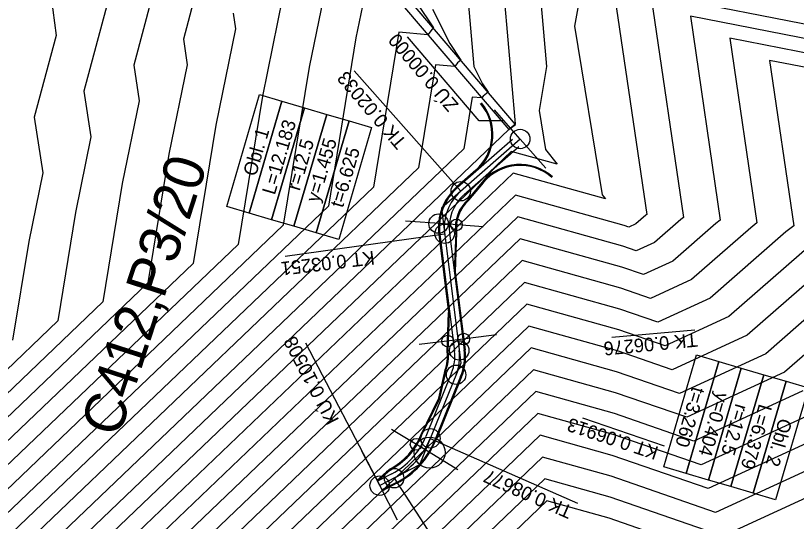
# Model space of a CAD drawing. Extents: x -549394 to -546608, y -1037055 to -1033629.
# Drawn here: x -547510.8 to -547310, y -1036162.3 to -1036032.2 of the extents above; entities that cross this region are included whole.
import ezdxf

# ---------------------------------------------------------------- set-up
doc = ezdxf.new("R2010")
doc.units = 0
for name, color, linetype in [('hlavni_vrst', 7, 'Continuous'), ('hrana_L', 7, 'Continuous'), ('norm_vrst', 7, 'Continuous'), ('POLYGONY_SITUACE_PO', 7, 'Continuous'), ('u_sirka_1_5m', 7, 'Continuous'), ('x_navrh_C412', 7, 'Continuous'), ('x_osa_C412', 7, 'Continuous'), ('x_popis_oblouky_C412', 7, 'Continuous'), ('x_popis_pricne_rezy_C412', 7, 'Continuous'), ('x_popis_velky_C412', 7, 'Continuous')]:
    doc.layers.add(name, color=color, linetype=linetype)

msp = doc.modelspace()

# ---------------------------------------------------------------- linework, layer by layer
at = {"layer": 'hlavni_vrst'}
for p, q in [((-547430.88, -1036023.9), (-547435.28, -1036045.47)), ((-547385.56, -1036022.8), (-547382.3, -1036060.1)), ((-547487.05, -1036028.71), (-547493.18, -1036051.67)), ((-547337.27, -1036032.37), (-547329.59, -1036084.85)), ((-547242.13, -1036051.11), (-547337.27, -1036032.37)), ((-547435.28, -1036045.47), (-547441.94, -1036086.16)), ((-547493.18, -1036051.67), (-547491.39, -1036063.41)), ((-547382.26, -1036060.17), (-547383.95, -1036061.55)), ((-547382.3, -1036060.1), (-547382.27, -1036060.15)), ((-547382.27, -1036060.15), (-547382.26, -1036060.17)), ((-547383.95, -1036061.55), (-547529.34, -1036200.56)), ((-547383.95, -1036061.55), (-547383.95, -1036061.55)), ((-547383.95, -1036061.55), (-547383.95, -1036061.55)), ((-547383.95, -1036061.55), (-547383.95, -1036061.55)), ((-547383.95, -1036061.55), (-547383.95, -1036061.55)), ((-547383.95, -1036061.55), (-547383.95, -1036061.55)), ((-547383.95, -1036061.55), (-547383.95, -1036061.55)), ((-547383.95, -1036061.55), (-547383.95, -1036061.55)), ((-547491.39, -1036063.41), (-547495.36, -1036082.87)), ((-547495.36, -1036082.87), (-547499.92, -1036110.77)), ((-547441.94, -1036086.16), (-547552.56, -1036191.93)), ((-547330.76, -1036085.74), (-547341.74, -1036095.35)), ((-547329.59, -1036084.85), (-547330.76, -1036085.74)), ((-547381.07, -1036089.63), (-547506.12, -1036209.19)), ((-547354.88, -1036096.94), (-547381.07, -1036089.63)), ((-547285.75, -1036091.08), (-547317.86, -1036119.19)), ((-547341.74, -1036095.35), (-547349.34, -1036098.86)), ((-547349.34, -1036098.86), (-547354.88, -1036096.94)), ((-547499.92, -1036110.77), (-547575.78, -1036183.3)), ((-547378.19, -1036117.71), (-547482.89, -1036217.82)), ((-547356.25, -1036123.83), (-547378.19, -1036117.71)), ((-547317.86, -1036119.19), (-547340.07, -1036129.43)), ((-547340.07, -1036129.43), (-547356.25, -1036123.83)), ((-547293.98, -1036143.02), (-547330.8, -1036160)), ((-547375.3, -1036145.78), (-547459.67, -1036226.45)), ((-547357.63, -1036150.72), (-547375.3, -1036145.78)), ((-547330.8, -1036160), (-547357.63, -1036150.72))]:
    msp.add_line(p, q, dxfattribs=at)
at = {"layer": 'hrana_L'}
for p, q in [((-547382.19, -1036060.25), (-547409.46, -1036028.18)), ((-547411.32, -1036029.57), (-547383.95, -1036061.55)), ((-547383.95, -1036061.55), (-547382.19, -1036060.25))]:
    msp.add_line(p, q, dxfattribs=at)
at = {"layer": 'norm_vrst'}
for p, q in [((-547460.45, -1036011.4), (-547467.63, -1036038.31)), ((-547473.75, -1036020.05), (-547480.4, -1036044.99)), ((-547502.52, -1036020.73), (-547500.35, -1036037.36)), ((-547376.33, -1036021.55), (-547374.26, -1036045.33)), ((-547357.62, -1036020.99), (-547348.49, -1036083.4)), ((-547394.78, -1036024.05), (-547392.92, -1036045.34)), ((-547441.87, -1036026.36), (-547447.29, -1036052.95)), ((-547347.44, -1036026.68), (-547339.04, -1036084.12)), ((-547243.31, -1036047.19), (-547347.44, -1036026.68)), ((-547421.58, -1036029.73), (-547423.26, -1036037.99)), ((-547407.54, -1036029.1), (-547403.29, -1036035.43)), ((-547403.54, -1036030.58), (-547399.12, -1036039.45)), ((-547366.24, -1036030.25), (-547367.03, -1036035)), ((-547454.86, -1036031.63), (-547454.25, -1036035.63)), ((-547454.25, -1036035.63), (-547459.31, -1036060.43)), ((-547412.23, -1036036.52), (-547418.74, -1036076.32)), ((-547404.79, -1036037.2), (-547412.23, -1036036.52)), ((-547403.67, -1036035.75), (-547404.79, -1036037.2)), ((-547403.29, -1036035.43), (-547403.67, -1036035.75)), ((-547367.03, -1036035), (-547359.98, -1036078.3)), ((-547500.35, -1036037.36), (-547505.95, -1036058.35)), ((-547467.63, -1036038.31), (-547466.63, -1036044.89)), ((-547423.26, -1036037.99), (-547430.34, -1036081.24)), ((-547327.09, -1036038.06), (-547320.14, -1036085.57)), ((-547240.95, -1036055.02), (-547327.09, -1036038.06)), ((-547399.12, -1036039.45), (-547396.28, -1036043.68)), ((-547397.1, -1036044.35), (-547397.84, -1036045.32)), ((-547396.28, -1036043.68), (-547397.1, -1036044.35)), ((-547316.91, -1036043.75), (-547310.69, -1036086.3)), ((-547239.78, -1036058.94), (-547316.91, -1036043.75)), ((-547480.4, -1036044.99), (-547479.01, -1036054.15)), ((-547466.63, -1036044.89), (-547471.32, -1036067.91)), ((-547402.8, -1036044.86), (-547407.14, -1036071.39)), ((-547397.84, -1036045.32), (-547402.8, -1036044.86)), ((-547392.92, -1036045.34), (-547390.7, -1036049.8)), ((-547374.26, -1036045.33), (-547376.15, -1036056.66)), ((-547390.7, -1036049.8), (-547389.27, -1036051.92)), ((-547389.27, -1036051.92), (-547390.52, -1036052.95)), ((-547479.01, -1036054.15), (-547483.34, -1036075.39)), ((-547447.29, -1036052.95), (-547453.53, -1036091.08)), ((-547393.38, -1036053.21), (-547395.55, -1036066.47)), ((-547390.9, -1036053.43), (-547393.38, -1036053.21)), ((-547390.52, -1036052.95), (-547390.9, -1036053.43)), ((-547376.15, -1036056.66), (-547374.52, -1036066.65)), ((-547505.95, -1036058.35), (-547503.77, -1036072.68)), ((-547459.31, -1036060.43), (-547465.13, -1036096)), ((-547395.55, -1036066.47), (-547533.98, -1036198.84)), ((-547374.52, -1036066.65), (-547371.54, -1036070.47)), ((-547383.37, -1036067.17), (-547524.69, -1036202.29)), ((-547471.32, -1036067.91), (-547476.73, -1036100.93)), ((-547371.54, -1036070.47), (-547383.37, -1036067.17)), ((-547407.14, -1036071.39), (-547538.63, -1036197.11)), ((-547382.8, -1036072.78), (-547520.05, -1036204.01)), ((-547503.77, -1036072.68), (-547507.37, -1036090.35)), ((-547359.12, -1036079.39), (-547382.8, -1036072.78)), ((-547418.74, -1036076.32), (-547543.27, -1036195.38)), ((-547483.34, -1036075.39), (-547488.33, -1036105.85)), ((-547382.22, -1036078.4), (-547515.4, -1036205.74)), ((-547354.33, -1036086.19), (-547382.22, -1036078.4)), ((-547359.98, -1036078.3), (-547359.12, -1036079.39)), ((-547430.34, -1036081.24), (-547547.91, -1036193.66)), ((-547381.64, -1036084.01), (-547510.76, -1036207.47)), ((-547354.6, -1036091.56), (-547381.64, -1036084.01)), ((-547348.76, -1036083.6), (-547351.29, -1036085.82)), ((-547348.49, -1036083.4), (-547348.76, -1036083.6)), ((-547339.76, -1036084.67), (-547346.52, -1036090.59)), ((-547339.04, -1036084.12), (-547339.76, -1036084.67)), ((-547353.05, -1036086.63), (-547354.33, -1036086.19)), ((-547351.29, -1036085.82), (-547353.05, -1036086.63)), ((-547321.76, -1036086.81), (-547336.97, -1036100.12)), ((-547320.14, -1036085.57), (-547321.76, -1036086.81)), ((-547310.69, -1036086.3), (-547312.76, -1036087.88)), ((-547312.76, -1036087.88), (-547332.19, -1036104.89)), ((-547507.37, -1036090.35), (-547511.52, -1036115.69)), ((-547346.52, -1036090.59), (-547351.19, -1036092.74)), ((-547303.76, -1036088.94), (-547327.42, -1036109.66)), ((-547294.76, -1036090.01), (-547322.64, -1036114.42)), ((-547453.53, -1036091.08), (-547557.2, -1036190.21)), ((-547351.19, -1036092.74), (-547354.6, -1036091.56)), ((-547276.75, -1036092.15), (-547313.09, -1036123.96)), ((-547465.13, -1036096), (-547561.85, -1036188.48)), ((-547380.49, -1036095.24), (-547501.47, -1036210.92)), ((-547355.15, -1036102.32), (-547380.49, -1036095.24)), ((-547379.92, -1036100.86), (-547496.83, -1036212.64)), ((-547355.43, -1036107.7), (-547379.92, -1036100.86)), ((-547336.97, -1036100.12), (-547347.49, -1036104.97)), ((-547476.73, -1036100.93), (-547566.49, -1036186.75)), ((-547347.49, -1036104.97), (-547355.15, -1036102.32)), ((-547332.19, -1036104.89), (-547345.63, -1036111.08)), ((-547488.33, -1036105.85), (-547571.14, -1036185.03)), ((-547379.34, -1036106.47), (-547492.18, -1036214.37)), ((-547355.7, -1036113.07), (-547379.34, -1036106.47)), ((-547345.63, -1036111.08), (-547355.43, -1036107.7)), ((-547327.42, -1036109.66), (-547343.78, -1036117.2)), ((-547378.76, -1036112.09), (-547487.54, -1036216.1)), ((-547355.98, -1036118.45), (-547378.76, -1036112.09)), ((-547343.78, -1036117.2), (-547355.7, -1036113.07)), ((-547322.64, -1036114.42), (-547341.92, -1036123.31)), ((-547341.92, -1036123.31), (-547355.98, -1036118.45)), ((-547377.61, -1036123.32), (-547478.25, -1036219.55)), ((-547356.53, -1036129.21), (-547377.61, -1036123.32)), ((-547313.09, -1036123.96), (-547338.22, -1036135.54)), ((-547377.03, -1036128.94), (-547473.61, -1036221.27)), ((-547356.81, -1036134.59), (-547377.03, -1036128.94)), ((-547308.31, -1036128.72), (-547336.36, -1036141.66)), ((-547338.22, -1036135.54), (-547356.53, -1036129.21)), ((-547376.46, -1036134.55), (-547468.96, -1036223)), ((-547357.08, -1036139.96), (-547376.46, -1036134.55)), ((-547336.36, -1036141.66), (-547356.81, -1036134.59)), ((-547303.54, -1036133.49), (-547334.51, -1036147.77)), ((-547298.76, -1036138.26), (-547332.65, -1036153.88)), ((-547375.88, -1036140.17), (-547464.32, -1036224.73)), ((-547357.36, -1036145.34), (-547375.88, -1036140.17)), ((-547334.51, -1036147.77), (-547357.08, -1036139.96)), ((-547332.65, -1036153.88), (-547357.36, -1036145.34)), ((-547289.21, -1036147.79), (-547328.95, -1036166.11)), ((-547374.73, -1036151.4), (-547455.03, -1036228.18)), ((-547357.91, -1036156.1), (-547374.73, -1036151.4)), ((-547374.15, -1036157.01), (-547450.38, -1036229.9)), ((-547358.18, -1036161.47), (-547374.15, -1036157.01)), ((-547328.95, -1036166.11), (-547357.91, -1036156.1)), ((-547327.09, -1036172.23), (-547358.18, -1036161.47))]:
    msp.add_line(p, q, dxfattribs=at)
at = {"layer": 'POLYGONY_SITUACE_PO'}
for centre in [(-547381.03, -1036063.98), (-547396.3, -1036077.4), (-547400.45, -1036088.34), (-547396.69, -1036118.35), (-547397.51, -1036124.61), (-547404.13, -1036140.96), (-547413.44, -1036151.19), (-547417.14, -1036153.12)]:
    msp.add_circle(centre, 2.5, dxfattribs=at)
at = {"layer": 'u_sirka_1_5m'}
for centre, radius in [((-547402.01, -1036085.72), 2.5), ((-547397.41, -1036086.07), 1.5), ((-547399.68, -1036115.95), 1.5), ((-547395.55, -1036115.43), 1.5), ((-547407.78, -1036142.5), 1.5), ((-547404.3, -1036144.62), 4)]:
    msp.add_circle(centre, radius, dxfattribs=at)
at = {"layer": 'x_navrh_C412'}
for p, q in [((-547383.03, -1036064.08), (-547397.12, -1036076.46)), ((-547381.41, -1036065.98), (-547395.47, -1036078.34)), ((-547392.44, -1036072.01), (-547397.29, -1036076.27)), ((-547394.41, -1036079.55), (-547387.96, -1036071.74)), ((-547394.23, -1036079.72), (-547390.5, -1036075.21)), ((-547401.69, -1036088.5), (-547397.93, -1036118.51)), ((-547399.21, -1036088.19), (-547395.45, -1036118.2)), ((-547397.61, -1036087.99), (-547397.97, -1036098.11)), ((-547397.36, -1036087.98), (-547397.72, -1036098.1)), ((-547399.78, -1036118.72), (-547399.43, -1036108.6)), ((-547399.53, -1036118.71), (-547399.18, -1036108.59)), ((-547398.67, -1036124.13), (-547405.29, -1036140.49)), ((-547400.4, -1036123.45), (-547402.13, -1036131)), ((-547400.16, -1036123.53), (-547401.89, -1036131.08)), ((-547396.35, -1036125.07), (-547402.97, -1036141.43)), ((-547406.52, -1036139.97), (-547402.13, -1036131)), ((-547406.29, -1036140.08), (-547401.89, -1036131.08)), ((-547414.63, -1036148.9), (-547417.84, -1036151.79)), ((-547414.48, -1036149.11), (-547417.69, -1036152)), ((-547414.01, -1036150.08), (-547417.69, -1036152)), ((-547412.86, -1036152.3), (-547416.57, -1036154.23)), ((-547412.75, -1036152.52), (-547416.45, -1036154.45))]:
    msp.add_line(p, q, dxfattribs=at)
for points in [[(-547401.94, -1036088.53), (-547399.43, -1036108.6)], [(-547397.72, -1036098.1), (-547395.2, -1036118.17)], [(-547396.12, -1036125.16), (-547402.74, -1036141.52)]]:
    msp.add_lwpolyline(points, dxfattribs=at)
for centre, radius, start, end in [((-547400.53, -1036062.81), 12.5, 311.2978, 40.3973), ((-547400.53, -1036062.81), 12.25, 311.2982, 40.3973), ((-547381.06, -1036083.01), 12.5, 47.9685, 140.444), ((-547381.06, -1036083.01), 12.25, 47.9685, 140.4439), ((-547388.05, -1036086.79), 14, 131.2978, 187.1428), ((-547388.05, -1036086.79), 13.75, 131.2978, 187.1428), ((-547388.05, -1036086.79), 11.25, 131.2978, 187.1428), ((-547388.05, -1036086.79), 9.64, 131.2978, 187.1428), ((-547388.05, -1036086.79), 9.39, 131.1766, 187.264), ((-547409.09, -1036119.91), 9.39, 337.8336, 7.264), ((-547409.09, -1036119.91), 9.64, 337.9549, 7.1428), ((-547409.09, -1036119.91), 11.25, 337.9549, 7.1428), ((-547409.09, -1036119.91), 13.75, 337.9549, 7.1428), ((-547409.09, -1036119.91), 14, 337.9549, 7.1428), ((-547422.67, -1036133.45), 17.42, 297.4888, 337.9549), ((-547422.67, -1036133.45), 17.67, 297.5923, 337.9549), ((-547422.67, -1036133.45), 18.75, 297.4888, 337.9549), ((-547422.67, -1036133.45), 21.25, 297.4888, 337.9549), ((-547422.67, -1036133.45), 21.5, 297.4888, 337.9549)]:
    msp.add_arc(centre, radius, start, end, dxfattribs=at)
at = {"layer": 'x_osa_C412'}
for points in [[(-547381.03, -1036063.98), (-547401.28, -1036081.77)], [(-547401.28, -1036081.77), (-547396.29, -1036121.58), (-547406.9, -1036147.79)], [(-547406.9, -1036147.79), (-547417.14, -1036153.12)]]:
    msp.add_lwpolyline(points, dxfattribs=at)
for centre, radius, start, end in [((-547388.05, -1036086.79), 12.5, 131.2978, 187.1428), ((-547409.09, -1036119.91), 12.5, 337.9549, 7.1428), ((-547422.67, -1036133.45), 20, 297.4888, 337.9549)]:
    msp.add_arc(centre, radius, start, end, dxfattribs=at)
at = {"layer": 'x_popis_oblouky_C412'}
for points in [[(-547385.19, -1036059.28), (-547391.57, -1036059.28), (-547410.04, -1036037.72)], [(-547423.74, -1036046.43), (-547396.3, -1036077.4)], [(-547385.19, -1036059.28), (-547381.03, -1036063.98)], [(-547441.42, -1036094.13), (-547400.45, -1036088.34)], [(-547357.45, -1036114.91), (-547336.13, -1036113.04)], [(-547436.21, -1036116.4), (-547417.14, -1036153.12)], [(-547365, -1036135.72), (-547344.03, -1036142.88)], [(-547404.13, -1036140.96), (-547366.27, -1036157.64)], [(-547413.44, -1036151.19), (-547391, -1036185.95)]]:
    msp.add_lwpolyline(points, dxfattribs=at)
for points in [[(-547456.47, -1036081.36), (-547448.03, -1036052.57), (-547442.27, -1036054.26), (-547450.72, -1036083.05)], [(-547450.72, -1036083.05), (-547442.27, -1036054.26), (-547436.52, -1036055.95), (-547444.96, -1036084.74)], [(-547444.96, -1036084.74), (-547436.52, -1036055.95), (-547430.76, -1036057.64), (-547439.2, -1036086.43)], [(-547439.2, -1036086.43), (-547430.76, -1036057.64), (-547425, -1036059.33), (-547433.44, -1036088.11)], [(-547433.44, -1036088.11), (-547425, -1036059.33), (-547419.24, -1036061.01), (-547427.69, -1036089.8)], [(-547329.93, -1036121.21), (-547338.37, -1036149.99), (-547344.13, -1036148.31), (-547335.69, -1036119.52)], [(-547324.17, -1036122.9), (-547332.62, -1036151.68), (-547338.37, -1036149.99), (-547329.93, -1036121.21)], [(-547318.42, -1036124.58), (-547326.86, -1036153.37), (-547332.62, -1036151.68), (-547324.17, -1036122.9)], [(-547312.66, -1036126.27), (-547321.1, -1036155.06), (-547326.86, -1036153.37), (-547318.42, -1036124.58)], [(-547306.9, -1036127.96), (-547315.34, -1036156.75), (-547321.1, -1036155.06), (-547312.66, -1036126.27)]]:
    msp.add_lwpolyline(points, close=True, dxfattribs=at)
at = {"layer": 'x_popis_pricne_rezy_C412'}
for points in [[(-547374.43, -1036071.49), (-547381.03, -1036063.98), (-547387.63, -1036056.47)], [(-547390.54, -1036086.6), (-547400.51, -1036085.83), (-547410.48, -1036085.07)], [(-547387.11, -1036114.37), (-547397.03, -1036115.62), (-547406.96, -1036116.86)], [(-547397.03, -1036149.03), (-547405.58, -1036143.84), (-547414.12, -1036138.64)], [(-547412.53, -1036161.99), (-547417.14, -1036153.12), (-547421.76, -1036144.25)]]:
    msp.add_lwpolyline(points, dxfattribs=at)

# ---------------------------------------------------------------- texts
at = {"layer": 'x_popis_oblouky_C412'}
for s, rotation, p in [('ZÚ 0.00000', 130.424, (-547396.69, -1036055.09)), ('TK 0.02033', 130.424, (-547410, -1036064.64)), ('L=12.183', 73.6771, (-547444.12, -1036078.52)), ('Obl. 1', 73.6771, (-547448.98, -1036073.75)), ('r=12.5', 73.6771, (-547437.74, -1036077.47)), ('y=1.455', 73.6771, (-547432.83, -1036080.49)), ('t=6.625', 73.6771, (-547426.61, -1036081.83)), ('KT 0.03251', 186.9181, (-547418.69, -1036092.73)), ('KÚ 0.10508', 117.5305, (-547427.49, -1036136.24)), ('TK 0.06276', 185.5137, (-547335.63, -1036113.87)), ('t=3.260', 253.6771, (-547336.77, -1036127.49)), ('y=0.404', 253.6771, (-547330.54, -1036128.83)), ('r=12.5', 253.6771, (-547325.63, -1036131.85)), ('L=6.379', 253.6771, (-547319.58, -1036131.92)), ('KT 0.06913', 161.6293, (-547345.21, -1036143.24)), ('Obl. 2', 253.6771, (-547314.4, -1036135.57)), ('TK 0.08677', 156.3137, (-547367.24, -1036158.53))]:
    msp.add_text(s, height=3.5, rotation=rotation, dxfattribs=at).set_placement(p)
at = {"layer": 'x_popis_velky_C412'}
msp.add_text('C412,P3/20', height=10.5, rotation=72.0942, dxfattribs=at).set_placement((-547484.19, -1036140.98))

doc.saveas('drawing.dxf')
